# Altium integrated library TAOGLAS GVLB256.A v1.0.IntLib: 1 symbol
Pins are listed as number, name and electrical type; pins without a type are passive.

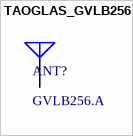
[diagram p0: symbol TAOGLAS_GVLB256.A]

## TAOGLAS_GVLB256.A
designator ANT?, comment GVLB256.A
GPS/GLONASS/BeiDou Single Feed Stacked Patch L1:1575MHz L5:1176.45MHz B1:1561MHz 25*25*6mm; ComponentLibStatus: Created; MFG: Taoglas; MFGPN: GVLB258.A; Temp_High: +85C; Temp_Low: -40C
footprint TAOGLAS_GVLB256.A (GPS/GLONASS/BeiDou Single Feed Stacked Patch L1:1575MHz L5:1176.45MHz B1:1561MHz 25*25*6mm)
pins: 1 RF FEED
